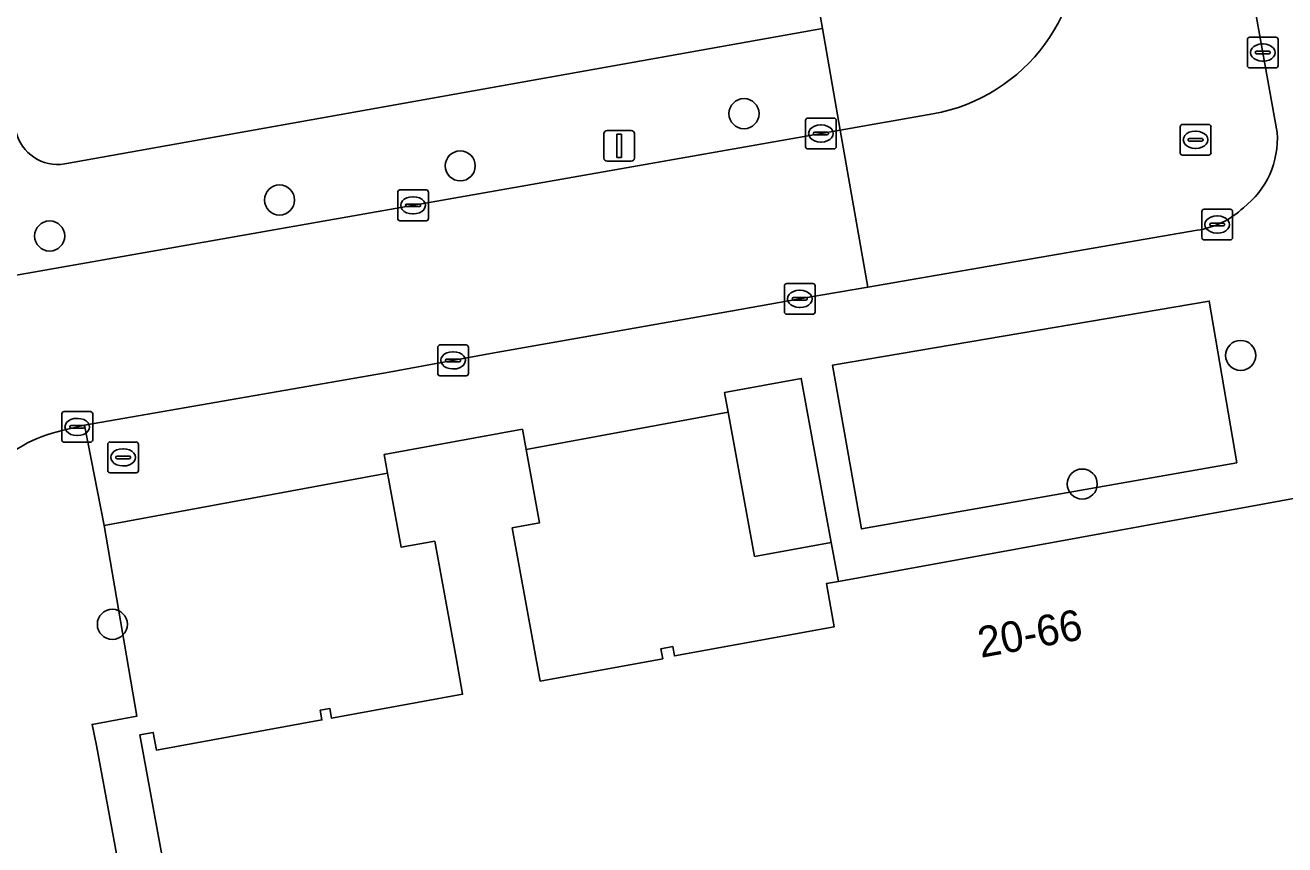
# Model space of a CAD drawing. Extents: x 157793 to 159380, y 380877 to 382313.
# Drawn here: x 158312.16 to 158353.15, y 381356.91 to 381383.59 of the extents above; entities that cross this region are included whole.
import ezdxf

# ---------------------------------------------------------------- set-up
doc = ezdxf.new("R2010")
doc.units = 0
for name, color, linetype in [('IMGEO_Boom', 7, 'Continuous'), ('IMGEO_Brandkraan', 7, 'Continuous'), ('IMGEO_Erf', 7, 'Continuous'), ('IMGEO_Kolk', 7, 'Continuous'), ('IMGEO_Lichtmast', 7, 'Continuous'), ('IMGEO_Pand', 7, 'Continuous'), ('IMGEO_Pand_nummerreeks', 7, 'Continuous'), ('IMGEO_Parkeervlak_open', 7, 'Continuous'), ('IMGEO_Rijbaan_lokaal_open', 7, 'Continuous'), ('IMGEO_Rioolput', 7, 'Continuous'), ('IMGEO_Voetpad_open', 7, 'Continuous')]:
    doc.layers.add(name, color=color, linetype=linetype)

msp = doc.modelspace()

# ---------------------------------------------------------------- linework, layer by layer
at = {"layer": 'IMGEO_Boom'}
for centre in [(158335.55, 381380.708), (158326.316, 381379.009), (158320.435, 381377.897), (158312.955, 381376.726), (158351.71, 381372.84), (158346.556, 381368.654), (158314.996, 381364.089)]:
    msp.add_circle(centre, 0.489, dxfattribs=at)
at = {"layer": 'IMGEO_Brandkraan'}
for p, q in [((158314.845, 381369.096), (158314.845, 381369.948)), ((158314.92, 381370.022), (158315.772, 381370.022)), ((158315.333, 381369.802), (158315.358, 381369.802)), ((158315.846, 381369.948), (158315.846, 381369.096)), ((158315.104, 381369.516), (158315.104, 381369.528)), ((158315.542, 381369.479), (158315.144, 381369.479)), ((158315.147, 381369.565), (158315.545, 381369.565)), ((158315.588, 381369.528), (158315.588, 381369.516)), ((158315.772, 381369.022), (158314.92, 381369.022)), ((158315.356, 381369.242), (158315.331, 381369.242))]:
    msp.add_line(p, q, dxfattribs=at)
for points in [[(158314.845, 381369.096), (158314.845, 381369.948)], [(158314.92, 381370.022), (158315.772, 381370.022)], [(158315.846, 381369.948), (158315.846, 381369.096)], [(158315.772, 381369.022), (158314.92, 381369.022)]]:
    msp.add_lwpolyline(points, dxfattribs=at)
for centre, radius, start, end in [((158314.922, 381369.946), 0.0765, 91.552, 178.448), ((158314.922, 381369.946), 0.0765, 91.552, 178.448), ((158315.77, 381369.946), 0.0765, 1.552, 88.448), ((158315.77, 381369.946), 0.0765, 1.552, 88.448), ((158315.144, 381369.525), 0.0403, 85.8775, 175.7526), ((158315.141, 381369.515), 0.0366, 178.938, 274.7102), ((158315.545, 381369.522), 0.043, 264.8664, 352.4533), ((158315.549, 381369.527), 0.0386, 1.7309, 96.639), ((158314.922, 381369.098), 0.0765, 181.552, 268.448), ((158314.922, 381369.098), 0.0765, 181.552, 268.448), ((158315.77, 381369.098), 0.0765, 271.552, 358.448), ((158315.77, 381369.098), 0.0765, 271.552, 358.448)]:
    msp.add_arc(centre, radius, start, end, dxfattribs=at)
for centre, major_axis, ratio, start_param, end_param in [((158315.332, 381369.522), (-0.387, 0.002), 0.722429, 4.712389, 7.853982), ((158315.357, 381369.522), (-0.39, 0.002), 0.717154, 1.570796, 4.712389)]:
    msp.add_ellipse(centre, major_axis=major_axis, ratio=ratio, start_param=start_param, end_param=end_param, dxfattribs=at)
at = {"layer": 'IMGEO_Erf'}
for points in [[(158313.449, 381379.074), (158338.102, 381383.483), (158335.126, 381400.425), (158333.81, 381407.731), (158331.077, 381423.054), (158329.812, 381429.85)], [(158317.947, 381349.249), (158315.895, 381360.491), (158316.327, 381360.57), (158316.432, 381359.994), (158321.815, 381360.976), (158321.758, 381361.29), (158322.074, 381361.348), (158322.131, 381361.034), (158326.394, 381361.812), (158326.179, 381362.993), (158325.485, 381366.794), (158324.396, 381366.595), (158323.954, 381369.012), (158314.726, 381367.306), (158315.791, 381361.097), (158314.336, 381360.831), (158314.484, 381360.147), (158317.956, 381341.359)]]:
    msp.add_lwpolyline(points, dxfattribs=at)
msp.add_lwpolyline([(158335.034, 381370.998), (158328.461, 381369.774), (158328.895, 381367.395), (158328.009, 381367.234), (158328.693, 381363.486), (158328.92, 381362.241), (158332.905, 381362.968), (158332.846, 381363.296), (158333.23, 381363.366), (158333.286, 381363.062), (158338.487, 381364.011), (158338.264, 381365.233), (158338.231, 381365.413), (158338.624, 381365.485), (158338.388, 381366.754), (158335.891, 381366.299)], close=True, dxfattribs=at)
msp.add_arc((158313.217, 381380.448), 1.394, 193.1593, 279.5771, dxfattribs=at)
at = {"layer": 'IMGEO_Kolk'}
for p, q in [((158337.552, 381379.636), (158337.552, 381380.488)), ((158337.627, 381380.562), (158338.479, 381380.562)), ((158338.553, 381380.488), (158338.553, 381379.636)), ((158337.811, 381380.056), (158337.811, 381380.068)), ((158338.249, 381380.019), (158337.851, 381380.019)), ((158337.854, 381380.105), (158338.252, 381380.105)), ((158338.04, 381380.342), (158338.065, 381380.342)), ((158338.295, 381380.068), (158338.295, 381380.056)), ((158338.479, 381379.562), (158337.627, 381379.562)), ((158338.063, 381379.782), (158338.038, 381379.782)), ((158324.28, 381377.298), (158324.28, 381378.15)), ((158324.355, 381378.224), (158325.207, 381378.224)), ((158324.768, 381378.004), (158324.793, 381378.004)), ((158325.281, 381378.15), (158325.281, 381377.298)), ((158324.539, 381377.718), (158324.539, 381377.73)), ((158324.977, 381377.681), (158324.579, 381377.681)), ((158324.582, 381377.767), (158324.98, 381377.767)), ((158325.023, 381377.73), (158325.023, 381377.718)), ((158350.446, 381376.672), (158350.446, 381377.524)), ((158350.521, 381377.598), (158351.373, 381377.598)), ((158351.447, 381377.524), (158351.447, 381376.672)), ((158325.207, 381377.224), (158324.355, 381377.224)), ((158324.791, 381377.444), (158324.766, 381377.444)), ((158350.705, 381377.092), (158350.705, 381377.104)), ((158350.748, 381377.141), (158351.146, 381377.141)), ((158350.934, 381377.378), (158350.959, 381377.378)), ((158351.189, 381377.104), (158351.189, 381377.092)), ((158351.143, 381377.055), (158350.745, 381377.055)), ((158350.957, 381376.818), (158350.932, 381376.818)), ((158351.373, 381376.598), (158350.521, 381376.598)), ((158336.863, 381374.253), (158336.863, 381375.105)), ((158336.938, 381375.179), (158337.79, 381375.179)), ((158337.864, 381375.105), (158337.864, 381374.253)), ((158337.122, 381374.673), (158337.122, 381374.685)), ((158337.56, 381374.636), (158337.162, 381374.636)), ((158337.165, 381374.722), (158337.563, 381374.722)), ((158337.351, 381374.959), (158337.376, 381374.959)), ((158337.606, 381374.685), (158337.606, 381374.673)), ((158337.374, 381374.399), (158337.349, 381374.399)), ((158337.79, 381374.179), (158336.938, 381374.179)), ((158325.582, 381372.253), (158325.582, 381373.105)), ((158325.657, 381373.179), (158326.509, 381373.179)), ((158326.583, 381373.105), (158326.583, 381372.253)), ((158325.841, 381372.673), (158325.841, 381372.685)), ((158326.279, 381372.636), (158325.881, 381372.636)), ((158325.884, 381372.722), (158326.282, 381372.722)), ((158326.07, 381372.959), (158326.095, 381372.959)), ((158326.325, 381372.685), (158326.325, 381372.673)), ((158326.509, 381372.179), (158325.657, 381372.179)), ((158326.093, 381372.399), (158326.068, 381372.399)), ((158313.354, 381370.086), (158313.354, 381370.938)), ((158313.429, 381371.012), (158314.281, 381371.012)), ((158314.355, 381370.938), (158314.355, 381370.086)), ((158313.656, 381370.555), (158314.054, 381370.555)), ((158313.842, 381370.792), (158313.867, 381370.792)), ((158313.613, 381370.506), (158313.613, 381370.518)), ((158314.051, 381370.469), (158313.653, 381370.469)), ((158313.865, 381370.232), (158313.84, 381370.232)), ((158314.097, 381370.518), (158314.097, 381370.506)), ((158314.281, 381370.012), (158313.429, 381370.012))]:
    msp.add_line(p, q, dxfattribs=at)
for points in [[(158337.552, 381379.636), (158337.552, 381380.488)], [(158337.627, 381380.562), (158338.479, 381380.562)], [(158338.553, 381380.488), (158338.553, 381379.636)], [(158338.479, 381379.562), (158337.627, 381379.562)], [(158324.28, 381377.298), (158324.28, 381378.15)], [(158324.355, 381378.224), (158325.207, 381378.224)], [(158325.281, 381378.15), (158325.281, 381377.298)], [(158350.446, 381376.672), (158350.446, 381377.524)], [(158350.521, 381377.598), (158351.373, 381377.598)], [(158351.447, 381377.524), (158351.447, 381376.672)], [(158325.207, 381377.224), (158324.355, 381377.224)], [(158351.373, 381376.598), (158350.521, 381376.598)], [(158336.863, 381374.253), (158336.863, 381375.105)], [(158336.938, 381375.179), (158337.79, 381375.179)], [(158337.864, 381375.105), (158337.864, 381374.253)], [(158337.79, 381374.179), (158336.938, 381374.179)], [(158325.582, 381372.253), (158325.582, 381373.105)], [(158325.657, 381373.179), (158326.509, 381373.179)], [(158326.583, 381373.105), (158326.583, 381372.253)], [(158326.509, 381372.179), (158325.657, 381372.179)], [(158313.354, 381370.086), (158313.354, 381370.938)], [(158313.429, 381371.012), (158314.281, 381371.012)], [(158314.355, 381370.938), (158314.355, 381370.086)], [(158314.281, 381370.012), (158313.429, 381370.012)]]:
    msp.add_lwpolyline(points, dxfattribs=at)
for centre, radius, start, end in [((158337.629, 381380.486), 0.0765, 91.552, 178.448), ((158337.629, 381380.486), 0.0765, 91.552, 178.448), ((158338.477, 381380.486), 0.0765, 1.552, 88.448), ((158338.477, 381380.486), 0.0765, 1.552, 88.448), ((158337.851, 381380.065), 0.0403, 85.8775, 175.7526), ((158337.848, 381380.055), 0.0366, 178.938, 274.7102), ((158338.252, 381380.062), 0.043, 264.8664, 352.4533), ((158338.256, 381380.067), 0.0386, 1.7309, 96.639), ((158337.629, 381379.638), 0.0765, 181.552, 268.448), ((158337.629, 381379.638), 0.0765, 181.552, 268.448), ((158338.477, 381379.638), 0.0765, 271.552, 358.448), ((158338.477, 381379.638), 0.0765, 271.552, 358.448), ((158324.357, 381378.148), 0.0765, 91.552, 178.448), ((158324.357, 381378.148), 0.0765, 91.552, 178.448), ((158325.205, 381378.148), 0.0765, 1.552, 88.448), ((158325.205, 381378.148), 0.0765, 1.552, 88.448), ((158324.579, 381377.727), 0.0403, 85.8775, 175.7526), ((158324.576, 381377.717), 0.0366, 178.938, 274.7102), ((158324.98, 381377.724), 0.043, 264.8664, 352.4533), ((158324.984, 381377.729), 0.0386, 1.7309, 96.639), ((158350.523, 381377.522), 0.0765, 91.552, 178.448), ((158350.523, 381377.522), 0.0765, 91.552, 178.448), ((158351.371, 381377.522), 0.0765, 1.552, 88.448), ((158351.371, 381377.522), 0.0765, 1.552, 88.448), ((158324.357, 381377.3), 0.0765, 181.552, 268.448), ((158324.357, 381377.3), 0.0765, 181.552, 268.448), ((158325.205, 381377.3), 0.0765, 271.552, 358.448), ((158325.205, 381377.3), 0.0765, 271.552, 358.448), ((158350.745, 381377.101), 0.0403, 85.8775, 175.7526), ((158350.742, 381377.091), 0.0366, 178.938, 274.7102), ((158351.146, 381377.098), 0.043, 264.8664, 352.4533), ((158351.15, 381377.103), 0.0386, 1.7309, 96.639), ((158350.523, 381376.674), 0.0765, 181.552, 268.448), ((158350.523, 381376.674), 0.0765, 181.552, 268.448), ((158351.371, 381376.674), 0.0765, 271.552, 358.448), ((158351.371, 381376.674), 0.0765, 271.552, 358.448), ((158336.94, 381375.103), 0.0765, 91.552, 178.448), ((158336.94, 381375.103), 0.0765, 91.552, 178.448), ((158337.788, 381375.103), 0.0765, 1.552, 88.448), ((158337.788, 381375.103), 0.0765, 1.552, 88.448), ((158337.162, 381374.682), 0.0403, 85.8775, 175.7526), ((158337.159, 381374.672), 0.0366, 178.938, 274.7102), ((158337.563, 381374.679), 0.043, 264.8664, 352.4533), ((158337.567, 381374.684), 0.0386, 1.7309, 96.639), ((158336.94, 381374.255), 0.0765, 181.552, 268.448), ((158336.94, 381374.255), 0.0765, 181.552, 268.448), ((158337.788, 381374.255), 0.0765, 271.552, 358.448), ((158337.788, 381374.255), 0.0765, 271.552, 358.448), ((158325.659, 381373.103), 0.0765, 91.552, 178.448), ((158325.659, 381373.103), 0.0765, 91.552, 178.448), ((158326.507, 381373.103), 0.0765, 1.552, 88.448), ((158326.507, 381373.103), 0.0765, 1.552, 88.448), ((158325.881, 381372.682), 0.0403, 85.8775, 175.7526), ((158325.878, 381372.672), 0.0366, 178.938, 274.7102), ((158326.282, 381372.679), 0.043, 264.8664, 352.4533), ((158326.286, 381372.684), 0.0386, 1.7309, 96.639), ((158325.659, 381372.255), 0.0765, 181.552, 268.448), ((158325.659, 381372.255), 0.0765, 181.552, 268.448), ((158326.507, 381372.255), 0.0765, 271.552, 358.448), ((158326.507, 381372.255), 0.0765, 271.552, 358.448), ((158313.431, 381370.936), 0.0765, 91.552, 178.448), ((158313.431, 381370.936), 0.0765, 91.552, 178.448), ((158314.279, 381370.936), 0.0765, 1.552, 88.448), ((158314.279, 381370.936), 0.0765, 1.552, 88.448), ((158313.653, 381370.515), 0.0403, 85.8775, 175.7526), ((158314.058, 381370.517), 0.0386, 1.7309, 96.639), ((158313.65, 381370.505), 0.0366, 178.938, 274.7102), ((158314.054, 381370.512), 0.043, 264.8664, 352.4533), ((158313.431, 381370.088), 0.0765, 181.552, 268.448), ((158313.431, 381370.088), 0.0765, 181.552, 268.448), ((158314.279, 381370.088), 0.0765, 271.552, 358.448), ((158314.279, 381370.088), 0.0765, 271.552, 358.448)]:
    msp.add_arc(centre, radius, start, end, dxfattribs=at)
for centre, major_axis, ratio, start_param, end_param in [((158338.039, 381380.062), (-0.387, 0.002), 0.722429, 4.712389, 7.853982), ((158338.064, 381380.062), (-0.39, 0.002), 0.717154, 1.570796, 4.712389), ((158324.767, 381377.724), (-0.387, 0.002), 0.722429, 4.712389, 7.853982), ((158324.792, 381377.724), (-0.39, 0.002), 0.717154, 1.570796, 4.712389), ((158350.933, 381377.098), (-0.387, 0.002), 0.722429, 4.712389, 7.853982), ((158350.958, 381377.098), (-0.39, 0.002), 0.717154, 1.570796, 4.712389), ((158337.35, 381374.679), (-0.387, 0.002), 0.722429, 4.712389, 7.853982), ((158337.375, 381374.679), (-0.39, 0.002), 0.717154, 1.570796, 4.712389), ((158326.069, 381372.679), (-0.387, 0.002), 0.722429, 4.712389, 7.853982), ((158326.094, 381372.679), (-0.39, 0.002), 0.717154, 1.570796, 4.712389), ((158313.841, 381370.512), (-0.387, 0.002), 0.722429, 4.712389, 7.853982), ((158313.866, 381370.512), (-0.39, 0.002), 0.717154, 1.570796, 4.712389)]:
    msp.add_ellipse(centre, major_axis=major_axis, ratio=ratio, start_param=start_param, end_param=end_param, dxfattribs=at)
at = {"layer": 'IMGEO_Lichtmast'}
for p, q in [((158330.992, 381379.26), (158330.992, 381380.06)), ((158330.992, 381380.06), (158330.992, 381379.26)), ((158331.092, 381380.16), (158331.882, 381380.16)), ((158331.882, 381380.16), (158331.092, 381380.16)), ((158331.982, 381380.06), (158331.982, 381379.26)), ((158331.982, 381379.26), (158331.982, 381380.06)), ((158331.882, 381379.16), (158331.092, 381379.16)), ((158331.092, 381379.16), (158331.882, 381379.16))]:
    msp.add_line(p, q, dxfattribs=at)
msp.add_lwpolyline([(158331.412, 381380.035), (158331.562, 381380.035), (158331.562, 381379.285), (158331.412, 381379.285), (158331.412, 381380.035)], dxfattribs=at)
for centre, start, end in [((158331.092, 381380.06), 90, 180), ((158331.092, 381380.06), 90, 180), ((158331.882, 381380.06), 0, 90), ((158331.882, 381380.06), 360, 90), ((158331.092, 381379.26), 180, 270), ((158331.092, 381379.26), 180, 270), ((158331.882, 381379.26), 270, 0), ((158331.882, 381379.26), 270, 0)]:
    msp.add_arc(centre, 0.1, start, end, dxfattribs=at)
at = {"layer": 'IMGEO_Pand'}
msp.add_lwpolyline([(158338.388, 381366.754), (158337.413, 381372.094), (158334.917, 381371.638), (158335.034, 381370.998), (158335.891, 381366.299)], close=True, dxfattribs=at)
msp.add_lwpolyline([(158356.806, 381368.803), (158352.37, 381367.993), (158338.624, 381365.485), (158338.231, 381365.413), (158338.264, 381365.233), (158338.487, 381364.011), (158333.286, 381363.062), (158333.23, 381363.366), (158332.846, 381363.296), (158332.905, 381362.968), (158328.92, 381362.241), (158328.693, 381363.486), (158328.009, 381367.234), (158328.895, 381367.395), (158328.461, 381369.774), (158328.34, 381370.438), (158323.844, 381369.617), (158323.954, 381369.012), (158324.396, 381366.595), (158325.485, 381366.794), (158326.179, 381362.993), (158326.394, 381361.812), (158322.131, 381361.034), (158322.074, 381361.348), (158321.758, 381361.29), (158321.815, 381360.976), (158316.432, 381359.994), (158316.327, 381360.57), (158315.895, 381360.491), (158317.947, 381349.249)], dxfattribs=at)
at = {"layer": 'IMGEO_Parkeervlak_open'}
msp.add_lwpolyline([(158339.372, 381367.195), (158351.583, 381369.345), (158350.686, 381374.61), (158338.432, 381372.523)], close=True, dxfattribs=at)
at = {"layer": 'IMGEO_Rijbaan_lokaal_open'}
for points in [[(158352.898, 381380.093), (158350.952, 381390.906), (158348.475, 381404.709), (158343.334, 381403.775), (158345.561, 381391.636), (158345.88, 381390.216), (158346.193, 381388.029), (158346.395, 381387.128)], [(158341.696, 381380.704), (158338.683, 381380.173), (158339.581, 381375.064), (158350.296, 381376.913)], [(158338.683, 381380.173), (158310.078, 381375.134), (158295.815, 381372.584), (158295.325, 381375.445), (158290.639, 381374.631), (158288.244, 381374.208), (158287.851, 381374.139), (158288.882, 381368.304), (158289.501, 381364.801), (158294.386, 381365.682), (158304.247, 381367.461), (158311.017, 381369.07)], [(158313.366, 381370.392), (158314.091, 381370.57), (158323.888, 381372.276), (158327.302, 381372.903), (158335.176, 381374.288), (158337.608, 381374.723), (158339.581, 381375.064), (158338.683, 381380.173)]]:
    msp.add_lwpolyline(points, dxfattribs=at)
for centre, radius, start, end in [((158340.702, 381386.362), 5.745, 279.9677, 7.6632), ((158350.065, 381379.896), 2.84, 307.6067, 3.9826), ((158349.865, 381379.702), 2.822, 278.7889, 313.2374), ((158314.273, 381366.033), 4.452, 101.7506, 136.9904)]:
    msp.add_arc(centre, radius, start, end, dxfattribs=at)
at = {"layer": 'IMGEO_Rioolput'}
for p, q in [((158351.929, 381382.27), (158351.929, 381383.122)), ((158352.004, 381383.196), (158352.856, 381383.196)), ((158352.417, 381382.976), (158352.442, 381382.976)), ((158352.93, 381383.122), (158352.93, 381382.27)), ((158352.188, 381382.69), (158352.188, 381382.702)), ((158352.626, 381382.653), (158352.228, 381382.653)), ((158352.231, 381382.739), (158352.629, 381382.739)), ((158352.44, 381382.416), (158352.415, 381382.416)), ((158352.672, 381382.702), (158352.672, 381382.69)), ((158352.856, 381382.196), (158352.004, 381382.196)), ((158349.819, 381380.358), (158350.671, 381380.358)), ((158349.744, 381379.432), (158349.744, 381380.284)), ((158350.232, 381380.138), (158350.257, 381380.138)), ((158350.745, 381380.284), (158350.745, 381379.432)), ((158350.003, 381379.852), (158350.003, 381379.864)), ((158350.441, 381379.815), (158350.043, 381379.815)), ((158350.046, 381379.901), (158350.444, 381379.901)), ((158350.255, 381379.578), (158350.23, 381379.578)), ((158350.487, 381379.864), (158350.487, 381379.852)), ((158350.671, 381379.358), (158349.819, 381379.358))]:
    msp.add_line(p, q, dxfattribs=at)
for points in [[(158351.929, 381382.27), (158351.929, 381383.122)], [(158352.004, 381383.196), (158352.856, 381383.196)], [(158352.93, 381383.122), (158352.93, 381382.27)], [(158352.856, 381382.196), (158352.004, 381382.196)], [(158349.819, 381380.358), (158350.671, 381380.358)], [(158349.744, 381379.432), (158349.744, 381380.284)], [(158350.745, 381380.284), (158350.745, 381379.432)], [(158350.671, 381379.358), (158349.819, 381379.358)]]:
    msp.add_lwpolyline(points, dxfattribs=at)
for centre, radius, start, end in [((158352.006, 381383.12), 0.0765, 91.552, 178.448), ((158352.006, 381383.12), 0.0765, 91.552, 178.448), ((158352.854, 381383.12), 0.0765, 1.552, 88.448), ((158352.854, 381383.12), 0.0765, 1.552, 88.448), ((158352.228, 381382.699), 0.0403, 85.8775, 175.7526), ((158352.225, 381382.689), 0.0366, 178.938, 274.7102), ((158352.629, 381382.696), 0.043, 264.8664, 352.4533), ((158352.633, 381382.701), 0.0386, 1.7309, 96.639), ((158352.006, 381382.272), 0.0765, 181.552, 268.448), ((158352.006, 381382.272), 0.0765, 181.552, 268.448), ((158352.854, 381382.272), 0.0765, 271.552, 358.448), ((158352.854, 381382.272), 0.0765, 271.552, 358.448), ((158349.821, 381380.282), 0.0765, 91.552, 178.448), ((158349.821, 381380.282), 0.0765, 91.552, 178.448), ((158350.669, 381380.282), 0.0765, 1.552, 88.448), ((158350.669, 381380.282), 0.0765, 1.552, 88.448), ((158350.043, 381379.861), 0.0403, 85.8775, 175.7526), ((158350.04, 381379.851), 0.0366, 178.938, 274.7102), ((158350.444, 381379.858), 0.043, 264.8664, 352.4533), ((158350.448, 381379.863), 0.0386, 1.7309, 96.639), ((158349.821, 381379.434), 0.0765, 181.552, 268.448), ((158349.821, 381379.434), 0.0765, 181.552, 268.448), ((158350.669, 381379.434), 0.0765, 271.552, 358.448), ((158350.669, 381379.434), 0.0765, 271.552, 358.448)]:
    msp.add_arc(centre, radius, start, end, dxfattribs=at)
for centre, major_axis, ratio, start_param, end_param in [((158352.416, 381382.696), (-0.387, 0.002), 0.722429, 4.712389, 7.853982), ((158352.441, 381382.696), (-0.39, 0.002), 0.717154, 1.570796, 4.712389), ((158350.231, 381379.858), (-0.387, 0.002), 0.722429, 4.712389, 7.853982), ((158350.256, 381379.858), (-0.39, 0.002), 0.717154, 1.570796, 4.712389)]:
    msp.add_ellipse(centre, major_axis=major_axis, ratio=ratio, start_param=start_param, end_param=end_param, dxfattribs=at)
at = {"layer": 'IMGEO_Voetpad_open'}
for points in [[(158326.38, 381450.312), (158325.692, 381451.847), (158323.708, 381450.89), (158316.546, 381465.245), (158316.267, 381466.353), (158312.782, 381473.207), (158311.062, 381472.396), (158322.317, 381449.765), (158322.717, 381448.96), (158323.394, 381447.598), (158323.416, 381447.554), (158328.448, 381437.436), (158329.812, 381429.85), (158331.077, 381423.054), (158333.81, 381407.731), (158335.126, 381400.425), (158338.102, 381383.483), (158338.683, 381380.173), (158341.696, 381380.704)], [(158345.326, 381422.192), (158347.848, 381408.128), (158348.475, 381404.709), (158350.952, 381390.906), (158352.898, 381380.093)], [(158310.078, 381375.134), (158338.683, 381380.173), (158338.102, 381383.483), (158313.449, 381379.074)], [(158350.296, 381376.913), (158339.581, 381375.064), (158337.608, 381374.723), (158335.176, 381374.288), (158327.302, 381372.903), (158323.888, 381372.276), (158314.091, 381370.57), (158314.726, 381367.306), (158323.954, 381369.012), (158323.844, 381369.617), (158328.34, 381370.438), (158328.461, 381369.774), (158335.034, 381370.998), (158334.917, 381371.638), (158337.413, 381372.094), (158338.388, 381366.754), (158338.624, 381365.485), (158352.37, 381367.993), (158356.806, 381368.803), (158356.519, 381370.377), (158357.816, 381372.291), (158356.938, 381377.106)], [(158326.241, 381294.61), (158326.727, 381294.678), (158325.91, 381299.279), (158325.478, 381299.231), (158324.348, 381306.061), (158324.843, 381306.147), (158324.049, 381310.615), (158323.544, 381310.549), (158322.287, 381317.305), (158322.836, 381317.359), (158322.044, 381321.821), (158321.564, 381321.754), (158319.664, 381332.039), (158318.952, 381335.902), (158317.956, 381341.359), (158314.484, 381360.147), (158314.336, 381360.831), (158315.791, 381361.097), (158314.726, 381367.306), (158314.091, 381370.57), (158313.366, 381370.392)]]:
    msp.add_lwpolyline(points, dxfattribs=at)
msp.add_lwpolyline([(158351.583, 381369.345), (158339.372, 381367.195), (158338.432, 381372.523), (158350.686, 381374.61)], close=True, dxfattribs=at)
for centre, radius, start, end in [((158340.702, 381386.362), 5.745, 279.9677, 7.6632), ((158313.217, 381380.448), 1.394, 193.1593, 279.5771), ((158350.065, 381379.896), 2.84, 307.6067, 3.9826), ((158349.865, 381379.702), 2.822, 278.7889, 313.2374), ((158314.273, 381366.033), 4.452, 101.7506, 136.9904)]:
    msp.add_arc(centre, radius, start, end, dxfattribs=at)

# ---------------------------------------------------------------- texts
at = {"layer": 'IMGEO_Pand_nummerreeks'}
msp.add_text('20-66', height=1, rotation=10.3428, dxfattribs=at).set_placement((158343.256, 381362.996))

doc.saveas('drawing.dxf')
